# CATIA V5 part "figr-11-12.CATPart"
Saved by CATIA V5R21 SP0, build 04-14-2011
Part number: Part1
Bounding box of the stored display mesh (mm): x -10 to 5, y -10.258 to 7.91, z -1.851 to 2.054
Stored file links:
  D:\CATIA V5R21 E-RESOURCES\CATIA-V5R21\catia-v5r21-prt\c11-catia-v5r21-prt\c11-catia-v5r21-figr-11-12.CATPart
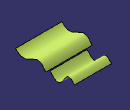
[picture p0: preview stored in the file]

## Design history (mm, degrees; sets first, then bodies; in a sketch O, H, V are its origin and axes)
Set1
  Sketch1 on yz-plane, origin (0, 0, 0), H (0, 1, 0), V (0, 0, 1)
    spline S1 through (-0.358, 0) (-3.1664, 2.0538) (-6.7822, 0.4079) (-10.2576, 1.6423)
    point P1 (-0.358, 0)
    coincidence: P1 H
  Extrude1: Element1 Sketch1, Lim1 5, Lim2 10, Direction yz-plane
  Sketch2 on yz-plane, origin (0, 0, 0), H (0, 1, 0), V (0, 0, 1)
    spline S1 through (0, 0) (3.5471, -1.4404) (5.7957, 1.2855) (7.9098, 0)
    point P1 (0, 0)
    point P2 (7.9098, 0)
    coincidence: P1 O, P2 H
  Extrude2: Element1 Sketch2, Lim1 4, Lim2 8, Direction yz-plane
Body1 (main body)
